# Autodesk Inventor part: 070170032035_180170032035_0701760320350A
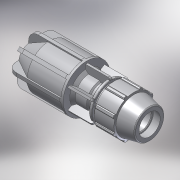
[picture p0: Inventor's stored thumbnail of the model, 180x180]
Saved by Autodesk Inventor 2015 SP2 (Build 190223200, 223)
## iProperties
Created: 2017-02
Part Number: 070170032035_180170032035_0701760320350A
Material: PVC-Piping
Description: PLASSON PLASS4 COUPLING 27-35*32
Document SubType Name: Modeling
Designer: KIM
Mass: 92.6774 g
Surface Area: 199.44 cm^2
Volume: 66.1981 cm^3
Density: 1.4 g/cm^3
Appearance: Smooth - White
Author: KIM
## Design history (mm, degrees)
derived "070170.ipt"
feature "Solid1::070170.ipt"
tag "TaggingFeature1"
body "Solid1"
other parameters: "d2" = 32, "d4" = 13.92857, "d5" = 23.45, "d7" = 64, "d8" = 40.53797, "d9" = 11.57143, "d11" = 4.875, "d12" = 51.2, "d13" = 120 deg, "d14" = 44.8, "d15" = 12 deg, "d16" = 57.6, "d18" = 1.6, "d19" = 35 deg, "d20" = 17.5 deg, "d21" = 59.52, "d23" = 0, "d25" = 360 deg, "d27" = 1.28, "d42" = 30.15, "d43" = 1.92, "d46" = 0.96, "d53" = 0.64, "d67" = 3.2, "d70" = 28.8, "d71" = 67, "d74" = 180 deg, "d75" = 35, "d76" = 83, "d80" = 28.8, "d84" = 78.85, "d85" = 135 deg, "d86" = 4.15, "d89" = 4.15, "d90" = 135 deg, "d94" = 4.15, "d97" = 5.12, "d98" = 0, "d100" = 360 deg, "d102" = 91.3, "d103" = 16.6, "d104" = 6.64, "d105" = 0, "d112" = 117, "d113" = 30.6, "d114" = 78, "d115" = 49.8, "d116" = 117, "d117" = 4.5, "d118" = 32, "d119" = 3.2, "d120" = 0, "d121" = 3.2, "d123" = 360 deg, "d_" = 32, "E_" = 64, "A_" = 81, "l_" = 67, "d_1" = 35, "E_1" = 83, "H_" = 195, "d106" = 40.53797
